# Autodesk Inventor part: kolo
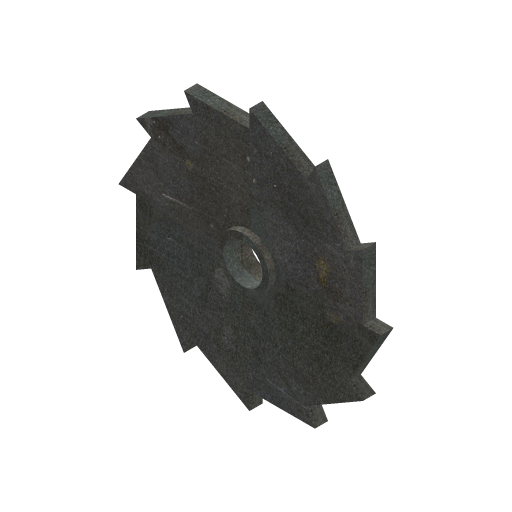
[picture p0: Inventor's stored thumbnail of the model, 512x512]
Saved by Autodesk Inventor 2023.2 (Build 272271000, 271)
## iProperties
Created: 2022-12
Part Number: kolo
Material: Stal
Document SubType Name: Modeling
Designer: TEST
Density: 7.85 g/cm^3
Appearance: Płyta
Mass: 2027.16 g
Surface Area: 612.971 cm^2
Volume: 258.237 cm^3
Author: TEST
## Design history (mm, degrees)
sketch "Szkic1"
  geometry: L1 (-100, 0)-(-86.603, 50); L2 (-86.603, 50)-(-50, 86.603); L3 (-50, 86.603)-(0, 100); L4 (0, 100)-(50, 86.603); L5 (50, 86.603)-(86.603, 50); L6 (86.603, 50)-(100, 0); L7 (100, 0)-(86.603, -50); L8 (86.603, -50)-(50, -86.603); L9 (50, -86.603)-(0, -100); L10 (0, -100)-(-50, -86.603); L11 (-50, -86.603)-(-86.603, -50); L12 (-86.603, -50)-(-100, 0); C1 r 15 at (0, 0); 2 further points
  constraints: 24 end point, 2 coincident, 1 centre point, 25 other
  dimensions: "d0" = 30 diameter of C1; "d4" = 200 distance of L6.end L1.start
extrude "Wyciągnięcie proste1" new body sketch "Szkic1" stored distance "d2" = 10; taper "d3" = 0 deg
sketch "Szkic3"
  geometry: L1 (0, 100)-(0, 86.603); L2 (-50, 86.603)-(0, 100) reference; L3 (-50, 86.603)-(0, 86.603); L4 (-50, 86.603)-(0, 100) reference; 2 further points
  constraints: 4 end point, 1 perpendicular, 1 vertical
extrude "Wyciągnięcie proste2" cut sketch "Szkic3" stored distance "d7" = 10; taper "d8" = 0 deg
pattern_circular "Szyk kołowy1" dims angle "d11" = 360 deg
sketch "Szkic4"
  geometry: C1 r 15 at (0, 0) reference; C2 r 20 at (0, 0); 1 further point
  constraints: 1 centre point, 1 coincident
  dimensions: "d13" = 40 diameter of C2
extrude "Wyciągnięcie proste3" join sketch "Szkic4" stored distance "d14" = 20; taper "d15" = 0 deg
node "Bryła1"
